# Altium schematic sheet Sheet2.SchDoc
size A4; SheetNumber: 3; SheetTotal: 3
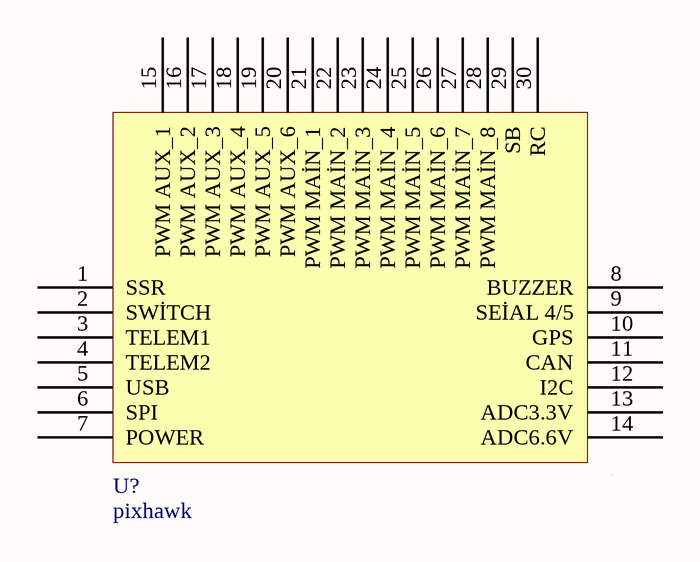
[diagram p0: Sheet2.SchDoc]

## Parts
U?  pixhawk

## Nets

Not connected (* = marked no-connect by the designer): U? 1(SSR) 2(SWİTCH) 3(TELEM1) 4(TELEM2) 5(USB) 6(SPI) 7(POWER) 8(BUZZER) 9(SEİAL_4/5) 10(GPS) 11(CAN) 12(I2C) 13(ADC3.3V) 14(ADC6.6V) 15(PWM_AUX_1) 16(PWM_AUX_2) 17(PWM_AUX_3) 18(PWM_AUX_4) 19(PWM_AUX_5) 20(PWM_AUX_6) 21(PWM_MAİN_1) 22(PWM_MAİN_2) 23(PWM_MAİN_3) 24(PWM_MAİN_4) 25(PWM_MAİN_5) 26(PWM_MAİN_6) 27(PWM_MAİN_7) 28(PWM_MAİN_8) 29(SB) 30(RC)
